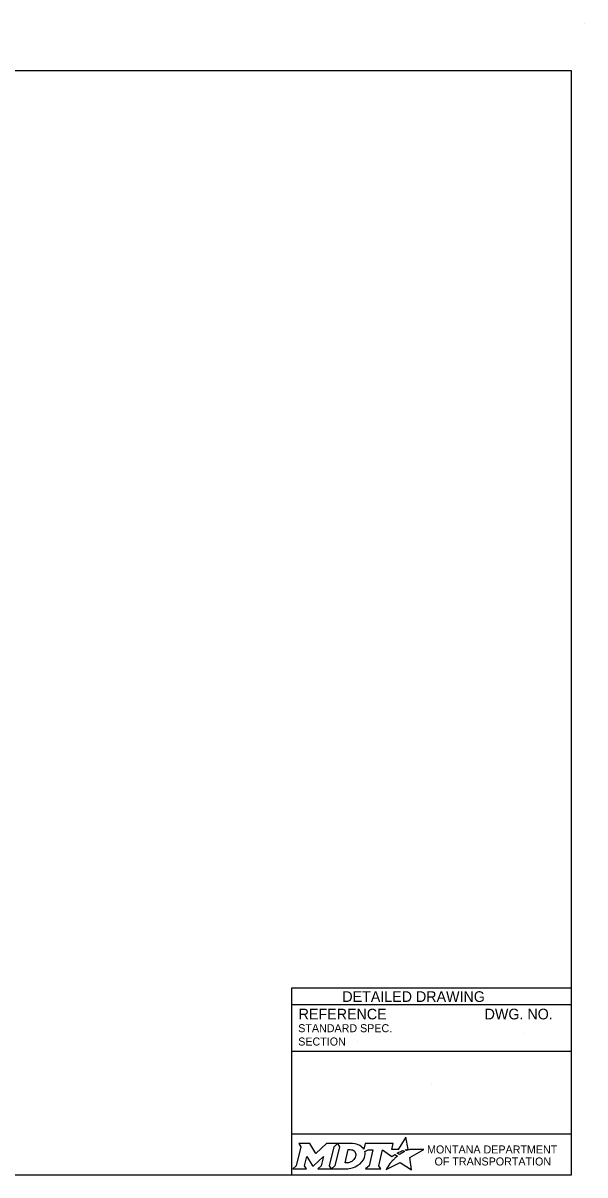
# Model space of a CAD drawing. Extents: x 49991.4 to 50029.7, y 49987.6 to 50011.4.
# Drawn here: x 50016.83 to 50021.04, y 49999.89 to 50008.52 of the extents above; entities that cross this region are included whole.
import ezdxf

# ---------------------------------------------------------------- set-up
doc = ezdxf.new("R2010")
doc.units = 0
for name, color, linetype in [('Default', 7, 'Continuous'), ('Level 1', 7, 'Continuous'), ('Level 4', 7, 'Continuous')]:
    doc.layers.add(name, color=color, linetype=linetype)

msp = doc.modelspace()

# ---------------------------------------------------------------- linework, layer by layer
at = {"layer": 'Default'}
for points in [[(50018.8933, 50000.1206), (50018.9074, 50000.0972), (50018.8739, 49999.9539), (50018.8482, 49999.9314), (50018.9498, 49999.9314), (50018.9363, 49999.9542), (50018.9525, 50000.0243), (50018.9962, 49999.9553), (50019.0015, 49999.9553), (50019.0766, 50000.0248), (50019.0602, 49999.9537), (50019.0355, 49999.9317), (50019.1371, 49999.9317), (50019.1233, 49999.955), (50019.1565, 50000.0974)], [(50019.1565, 50000.0974), (50019.1818, 50000.1206), (50019.0994, 50000.1206), (50019.0198, 50000.0476), (50018.9753, 50000.1203), (50018.8933, 50000.1206)], [(50019.2954, 50000.1206), (50019.1818, 50000.1206), (50019.1965, 50000.0977), (50019.1626, 49999.9539), (50019.1371, 49999.9317), (50019.2477, 49999.9317)], [(50019.7003, 50000.0679), (50019.69, 50000.0735), (50019.7016, 50000.0763), (50019.7132, 50000.0783), (50019.6958, 50000.1684), (50019.6363, 50000.0771), (50019.589, 50000.0764), (50019.5993, 50000.1205), (50019.3901, 50000.1206), (50019.38, 50000.0781), (50019.3742, 50000.0864)], [(50019.3194, 50000.0339), (50019.3182, 50000.0258), (50019.315, 50000.0165), (50019.3108, 50000.0083), (50019.3052, 50000.0008), (50019.2987, 49999.9939), (50019.2908, 49999.9876), (50019.2825, 49999.9829), (50019.2734, 49999.979), (50019.2643, 49999.9767), (50019.2551, 49999.9758), (50019.2392, 49999.9758), (50019.2628, 50000.0758), (50019.2788, 50000.0758), (50019.2864, 50000.0752), (50019.294, 50000.0733), (50019.3006, 50000.0703), (50019.3067, 50000.0661), (50019.3115, 50000.0611), (50019.3152, 50000.0551), (50019.3179, 50000.0489), (50019.3195, 50000.0415), (50019.3195, 50000.0385), (50019.3194, 50000.0339)], [(50019.3868, 50000.0615), (50019.4114, 50000.0746), (50019.4483, 50000.0746), (50019.4197, 49999.9541), (50019.3922, 49999.9314), (50019.5084, 49999.9314), (50019.4914, 49999.9543), (50019.5196, 50000.0745), (50019.5909, 50000.0228), (50019.612, 50000.0379), (50019.6317, 50000.027)], [(50019.5759, 49999.9711), (50019.5606, 49999.9467), (50019.5559, 49999.9392), (50019.5501, 49999.9306), (50019.5478, 49999.9263), (50019.6531, 49999.9794), (50019.737, 49999.9243), (50019.7239, 50000.017), (50019.8308, 50000.0754), (50019.7815, 50000.0762), (50019.7514, 50000.0766), (50019.7306, 50000.0769), (50019.7238, 50000.0754), (50019.7189, 50000.0742), (50019.7105, 50000.0719), (50019.7003, 50000.0679)], [(50019.6499, 50000.0403), (50019.6475, 50000.0386), (50019.6292, 50000.0482), (50019.6395, 50000.0539), (50019.6436, 50000.0561), (50019.6522, 50000.0601), (50019.6579, 50000.0627), (50019.6658, 50000.0657), (50019.6731, 50000.0684), (50019.6849, 50000.061), (50019.6809, 50000.0589), (50019.6763, 50000.0564), (50019.6721, 50000.0542), (50019.6671, 50000.0513), (50019.6652, 50000.0502), (50019.6625, 50000.0486), (50019.66, 50000.0472), (50019.6577, 50000.0456), (50019.6551, 50000.0438), (50019.6524, 50000.042), (50019.6499, 50000.0403)], [(50019.2934, 49999.939), (50019.3018, 49999.9416), (50019.3148, 49999.947), (50019.3352, 49999.958)], [(50019.5898, 49999.9872), (50019.5898, 49999.9872)]]:
    msp.add_lwpolyline(points, dxfattribs=at)
for centre, radius, start, end in [((50019.3185, 50000.0422), 0.0709, 339.53292, 15.85821), ((50019.2745, 50000.0595), 0.1183, 300.91025, 339.13831)]:
    msp.add_arc(centre, radius, start, end, dxfattribs=at)
for centre, major_axis, ratio, start_param, end_param in [((50019.2933, 50000.0732), (0.0834, -0.0037), 0.568097, 0.61298, 1.570796), ((50019.3489, 50000.0805), (0.0361, -0.0295), 0.469099, 1.225588, 1.570796), ((50019.6206, 50000.0173), (-0.0112, -0.0097), 0.021651, 3.157348, 6.283185), ((50019.5829, 49999.9791), (-0.00694, -0.00806), 0.008222, 0, 3.137361), ((50019.5996, 49999.9974), (-0.0098, -0.0102), 0.016458, 3.141593, 6.279097), ((50019.248, 50000.08), (0, 0.1484), 0.987302, 3.139398, 3.456847)]:
    msp.add_ellipse(centre, major_axis=major_axis, ratio=ratio, start_param=start_param, end_param=end_param, dxfattribs=at)
at = {"layer": 'Level 1'}
msp.add_line((50021.0378, 50008.5236), (50021.0378, 50008.5236), dxfattribs=at)
msp.add_lwpolyline([(50020.9378, 50008.1646), (50009.7374, 50008.1646), (50009.7374, 49999.8856), (50020.9378, 49999.8856)], close=True, dxfattribs=at)
at = {"layer": 'Level 4'}
for p, q in [((50020.9378, 50001.2856), (50018.8378, 50001.2856)), ((50018.8378, 50001.2856), (50018.8378, 49999.8856)), ((50020.9378, 50001.1606), (50018.8378, 50001.1606)), ((50020.5739, 50000.9455), (50020.5739, 50000.9455)), ((50020.9378, 50000.8106), (50018.8378, 50000.8106)), ((50019.3321, 50000.8861), (50019.3321, 50000.8861)), ((50019.8878, 50000.5615), (50019.8878, 50000.5615)), ((50020.9378, 50000.1925), (50018.8378, 50000.1925))]:
    msp.add_line(p, q, dxfattribs=at)

# ---------------------------------------------------------------- texts
at = {"layer": 'Default'}
for s, p in [('MONTANA DEPARTMENT', (50019.854, 50000.0468)), ('OF TRANSPORTATION', (50019.9102, 49999.9568))]:
    msp.add_text(s, height=0.06, dxfattribs=at).set_placement(p)
at = {"layer": 'Level 4'}
for s, height, p in [('DETAILED DRAWING', 0.0799, (50019.2188, 50001.1831)), ('REFERENCE', 0.08, (50018.8914, 50001.0522)), ('DWG. NO.', 0.08, (50020.2856, 50001.0522)), ('STANDARD SPEC.', 0.06, (50018.8881, 50000.9562)), ('SECTION', 0.06, (50018.8881, 50000.8562))]:
    msp.add_text(s, height=height, dxfattribs=at).set_placement(p)

doc.saveas('drawing.dxf')
